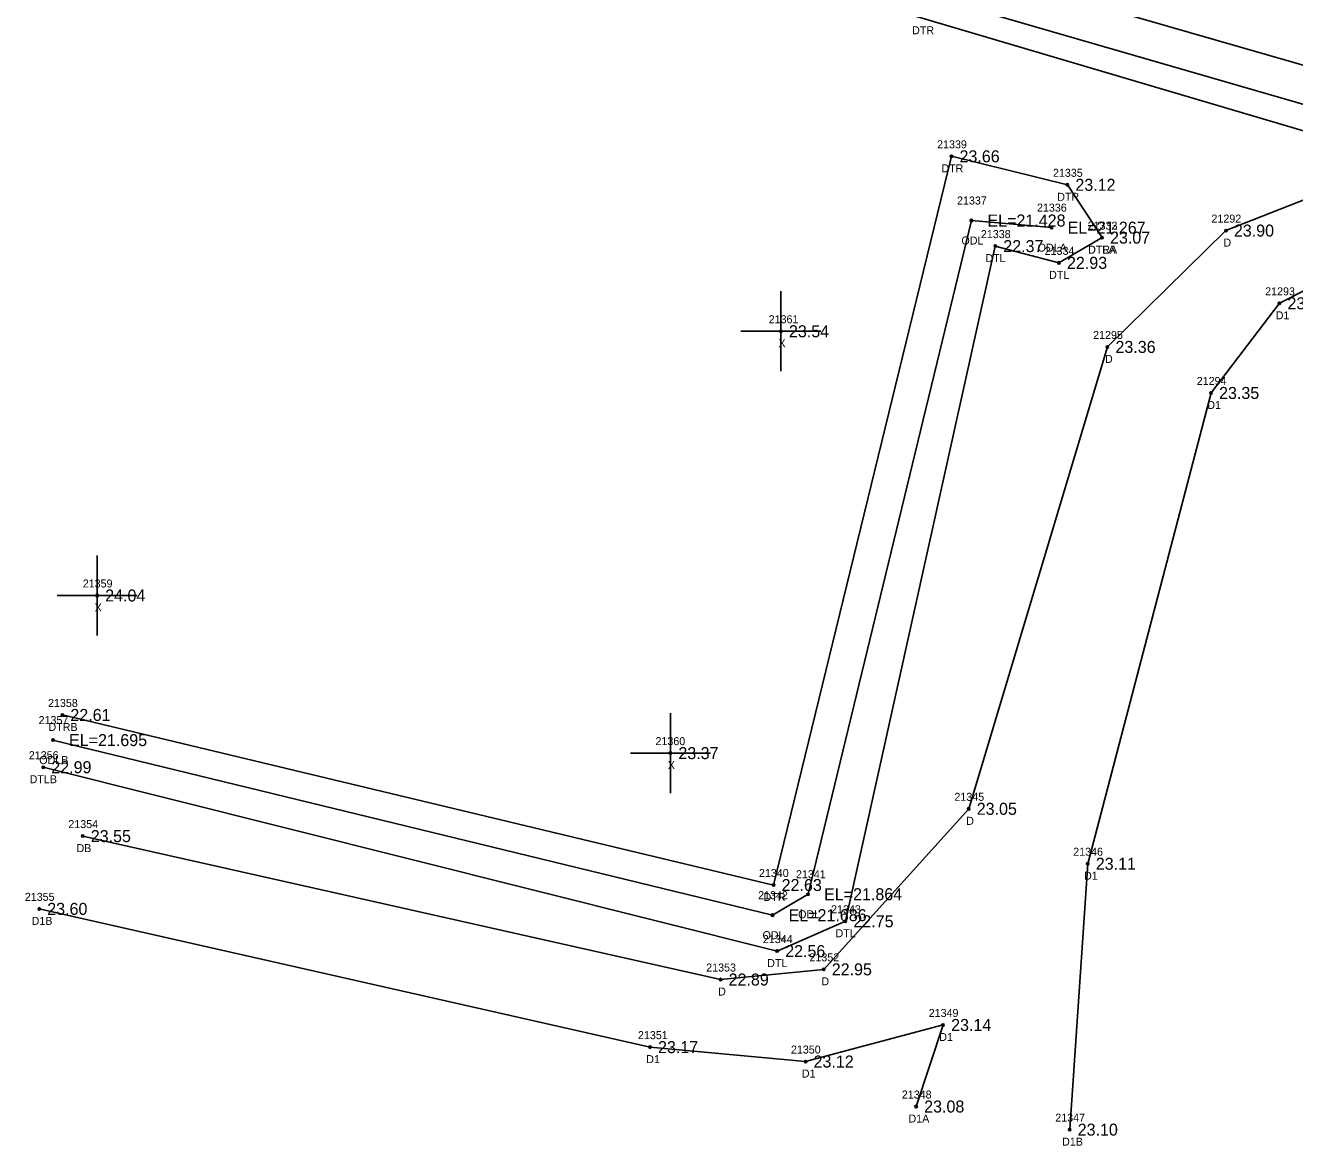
# Model space of a CAD drawing. Extents: x 2655177 to 2656219, y 761780 to 764748.
# Drawn here: x 2655443.1 to 2655601.7, y 763807.5 to 763947.5 of the extents above; entities that cross this region are included whole.
import ezdxf

# ---------------------------------------------------------------- set-up
doc = ezdxf.new("R2010")
doc.units = 0
for name, color, linetype in [('RD_EX_Driveway', 7, 'Continuous'), ('RD_EX_Driveway_txCode', 7, 'Continuous'), ('RD_EX_H2O', 7, 'Continuous'), ('RD_EX_H2O_txCode', 7, 'Continuous'), ('RD_EX_Misc', 7, 'Continuous'), ('RD_EX_Misc_txCode', 7, 'Continuous'), ('RD_EX_TX_Driveway_ELEV', 7, 'Continuous'), ('RD_EX_TX_H2O_ELEV', 7, 'Continuous'), ('RD_EX_TX_Misc_ELEV', 7, 'Continuous'), ('RD_SMD_Locator', 7, 'Continuous')]:
    doc.layers.add(name, color=color, linetype=linetype)

msp = doc.modelspace()

# ---------------------------------------------------------------- linework, layer by layer
at = {"layer": 'RD_EX_Driveway'}
for points in [[(2655759.7, 763884.33), (2655653.19, 763917.62), (2655626.34, 763925.63), (2655605.55, 763926.69), (2655593.12, 763921.81), (2655578.32, 763907.27), (2655560.98, 763849.55), (2655542.86, 763829.49), (2655529.97, 763828.22), (2655450.25, 763846.14)], [(2655756.57, 763873.51), (2655649.82, 763907.87), (2655623.82, 763915.03), (2655607.22, 763916.49), (2655599.82, 763912.72), (2655591.27, 763901.52), (2655575.86, 763842.69), (2655573.6, 763809.46)], [(2655554.41, 763812.35), (2655557.78, 763822.54), (2655540.59, 763817.97), (2655521.15, 763819.77), (2655444.81, 763837.05)]]:
    msp.add_lwpolyline(points, dxfattribs=at)
at = {"layer": 'RD_EX_H2O'}
for points in [[(2655761.3, 763896.61), (2655655.94, 763927.18), (2655556.7, 763955.75), (2655492.71, 763974.97), (2655490.34, 763966.93)], [(2655760.74, 763891.62), (2655654.45, 763922.64), (2655555.92, 763951.2), (2655495.53, 763969.95)], [(2655761.29, 763886.78), (2655653.57, 763919.29), (2655555.16, 763948.34), (2655490.34, 763966.93)], [(2655577.64, 763920.93), (2655573.31, 763927.53), (2655558.83, 763931.09), (2655536.6, 763840.03), (2655447.7, 763861.28)], [(2655571.33, 763922.18), (2655561.32, 763923.07), (2655540.9, 763838.88), (2655536.46, 763836.26), (2655446.53, 763858.14)], [(2655577.64, 763920.93), (2655572.26, 763917.78), (2655564.3, 763919.87), (2655545.57, 763835.5), (2655537.04, 763831.77), (2655445.32, 763854.75)]]:
    msp.add_lwpolyline(points, dxfattribs=at)
at = {"layer": 'RD_EX_Misc'}
for p, q in [((2655537.51, 763904.23), (2655537.51, 763914.23)), ((2655532.51, 763909.23), (2655542.51, 763909.23)), ((2655452.05, 763871.21), (2655452.05, 763881.21)), ((2655447.05, 763876.21), (2655457.05, 763876.21)), ((2655523.69, 763851.51), (2655523.69, 763861.51)), ((2655518.69, 763856.51), (2655528.69, 763856.51))]:
    msp.add_line(p, q, dxfattribs=at)
at = {"layer": 'RD_SMD_Locator'}
for centre in [(2655558.83, 763931.09), (2655573.31, 763927.53), (2655561.32, 763923.07), (2655571.33, 763922.18), (2655577.64, 763920.93), (2655577.64, 763920.93), (2655593.12, 763921.81), (2655564.3, 763919.87), (2655572.26, 763917.78), (2655599.82, 763912.72), (2655537.51, 763909.23), (2655578.32, 763907.27), (2655591.27, 763901.52), (2655452.05, 763876.21), (2655447.7, 763861.28), (2655446.53, 763858.14), (2655523.69, 763856.51), (2655445.32, 763854.75), (2655560.98, 763849.55), (2655450.25, 763846.14), (2655575.86, 763842.69), (2655536.6, 763840.03), (2655540.9, 763838.88), (2655444.81, 763837.05), (2655536.46, 763836.26), (2655545.57, 763835.5), (2655537.04, 763831.77), (2655542.86, 763829.49), (2655529.97, 763828.22), (2655557.78, 763822.54), (2655521.15, 763819.77), (2655540.59, 763817.97), (2655554.41, 763812.35), (2655573.6, 763809.46)]:
    msp.add_circle(centre, 0.15, dxfattribs=at)

# ---------------------------------------------------------------- texts
at = {"layer": 'RD_EX_Driveway_txCode'}
for s, p in [('21292', (2655591.32, 763922.81)), ('D', (2655592.81, 763919.81)), ('21293', (2655598.03, 763913.72)), ('D1', (2655599.35, 763910.72)), ('21295', (2655576.53, 763908.27)), ('D', (2655578.01, 763905.27)), ('21294', (2655589.48, 763902.52)), ('D1', (2655590.8, 763899.52)), ('21345', (2655559.19, 763850.55)), ('21354', (2655448.45, 763847.14)), ('D', (2655560.67, 763847.55)), ('DB', (2655449.47, 763844.14)), ('21346', (2655574.04, 763843.69)), ('D1', (2655575.39, 763840.69)), ('21355', (2655443.01, 763838.05)), ('D1B', (2655443.86, 763835.05)), ('21352', (2655541.07, 763830.49)), ('21353', (2655528.17, 763829.22)), ('D', (2655542.56, 763827.49)), ('D', (2655529.66, 763826.22)), ('21349', (2655555.98, 763823.54)), ('21351', (2655519.64, 763820.77)), ('D1', (2655557.3, 763820.54)), ('21350', (2655538.76, 763818.97)), ('D1', (2655520.68, 763817.77)), ('D1', (2655540.12, 763815.97)), ('21348', (2655552.62, 763813.35)), ('D1A', (2655553.45, 763810.35)), ('21347', (2655571.8, 763810.46)), ('D1B', (2655572.65, 763807.46))]:
    msp.add_text(s, height=1, dxfattribs=at).set_placement(p)
at = {"layer": 'RD_EX_H2O_txCode'}
for s, p in [('DTR', (2655553.9, 763946.34)), ('21339', (2655557.03, 763932.09)), ('DTR', (2655557.56, 763929.09)), ('21335', (2655571.51, 763928.53)), ('21337', (2655559.52, 763925.07)), ('DTR', (2655572.04, 763925.53)), ('21336', (2655569.51, 763924.18)), ('21332', (2655575.85, 763921.93)), ('21333', (2655575.85, 763921.93)), ('ODL', (2655560.07, 763920.07)), ('21338', (2655562.5, 763920.87)), ('ODLA', (2655569.59, 763919.18)), ('21334', (2655570.47, 763918.78)), ('DTRA', (2655575.89, 763918.93)), ('DTLA', (2655575.91, 763918.93)), ('DTL', (2655563.06, 763917.87)), ('DTL', (2655571.02, 763915.78)), ('21358', (2655445.91, 763862.28)), ('21357', (2655444.73, 763860.14)), ('DTRB', (2655445.96, 763859.28)), ('21356', (2655443.51, 763855.75)), ('ODLB', (2655444.81, 763855.14)), ('DTLB', (2655443.61, 763852.75)), ('21340', (2655534.76, 763841.03)), ('21341', (2655539.39, 763840.88)), ('21342', (2655534.66, 763838.26)), ('DTR', (2655535.33, 763838.03)), ('21343', (2655543.78, 763836.5)), ('ODL', (2655539.66, 763835.88)), ('ODL', (2655535.21, 763833.26)), ('21344', (2655535.25, 763832.77)), ('DTL', (2655544.33, 763833.5)), ('DTL', (2655535.8, 763829.77))]:
    msp.add_text(s, height=1, dxfattribs=at).set_placement(p)
at = {"layer": 'RD_EX_Misc_txCode'}
for s, p in [('21361', (2655535.98, 763910.23)), ('X', (2655537.2, 763907.23)), ('21359', (2655450.25, 763877.21)), ('X', (2655451.73, 763874.21)), ('21360', (2655521.83, 763857.51)), ('X', (2655523.37, 763854.51))]:
    msp.add_text(s, height=1, dxfattribs=at).set_placement(p)
at = {"layer": 'RD_EX_TX_Driveway_ELEV'}
for s, p in [('23.90', (2655594.12, 763921.06)), ('23.54', (2655600.82, 763911.97)), ('23.36', (2655579.32, 763906.52)), ('23.35', (2655592.27, 763900.77)), ('23.05', (2655561.98, 763848.8)), ('23.55', (2655451.25, 763845.39)), ('23.11', (2655576.86, 763841.94)), ('23.60', (2655445.81, 763836.3)), ('22.95', (2655543.86, 763828.74)), ('22.89', (2655530.97, 763827.47)), ('23.14', (2655558.78, 763821.79)), ('23.17', (2655522.15, 763819.02)), ('23.12', (2655541.59, 763817.22)), ('23.08', (2655555.41, 763811.6)), ('23.10', (2655574.6, 763808.71))]:
    msp.add_text(s, height=1.5, dxfattribs=at).set_placement(p)
at = {"layer": 'RD_EX_TX_H2O_ELEV'}
for s, p in [('23.66', (2655559.83, 763930.34)), ('23.12', (2655574.31, 763926.78)), ('EL=21.428', (2655563.32, 763922.32)), ('EL=21.267', (2655573.33, 763921.43)), ('23.07', (2655578.64, 763920.18)), ('23.07', (2655578.64, 763920.18)), ('22.37', (2655565.3, 763919.12)), ('22.93', (2655573.26, 763917.03)), ('22.61', (2655448.7, 763860.53)), ('EL=21.695', (2655448.53, 763857.39)), ('22.99', (2655446.32, 763854)), ('22.63', (2655537.6, 763839.28)), ('EL=21.864', (2655542.9, 763838.13)), ('EL=21.686', (2655538.46, 763835.51)), ('22.75', (2655546.57, 763834.75)), ('22.56', (2655538.04, 763831.02))]:
    msp.add_text(s, height=1.5, dxfattribs=at).set_placement(p)
at = {"layer": 'RD_EX_TX_Misc_ELEV'}
for s, p in [('23.54', (2655538.51, 763908.48)), ('24.04', (2655453.05, 763875.46)), ('23.37', (2655524.69, 763855.76))]:
    msp.add_text(s, height=1.5, dxfattribs=at).set_placement(p)

doc.saveas('drawing.dxf')
